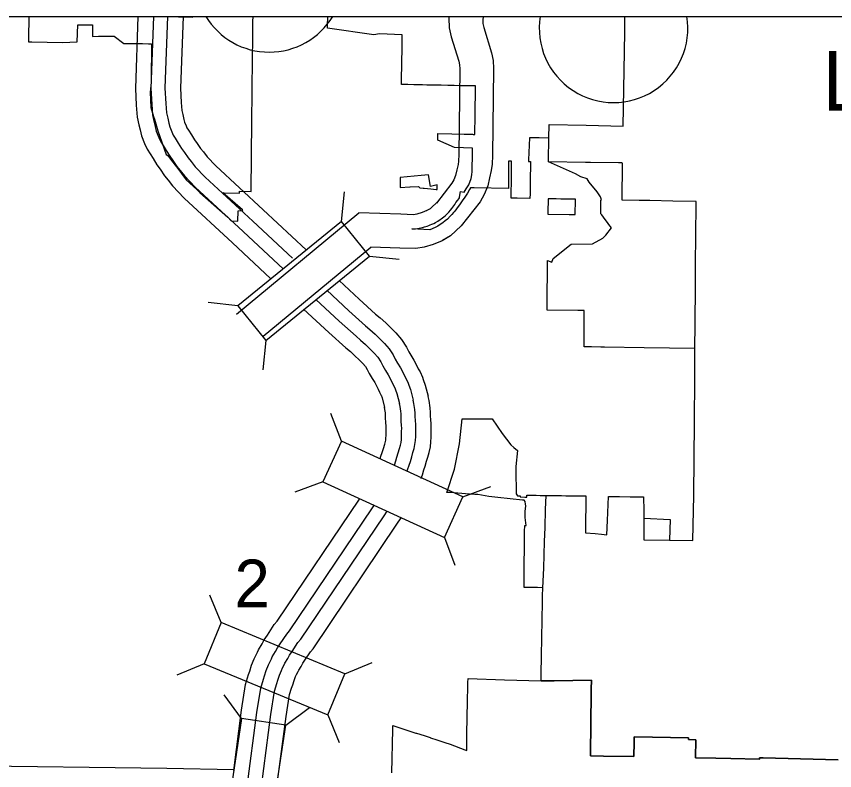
# Model space of a CAD drawing. Extents: x 670147 to 673275, y 705573 to 707613.
# Drawn here: x 670452.9 to 670561.9, y 707421.2 to 707521.7 of the extents above; entities that cross this region are included whole.
import ezdxf

# ---------------------------------------------------------------- set-up
doc = ezdxf.new("R2010")
doc.units = 0
for name, color, linetype in [('10', 7, 'Continuous'), ('19', 7, 'Continuous'), ('20', 7, 'Continuous'), ('27', 7, 'Continuous'), ('6', 7, 'Continuous'), ('R_NoPlot', 7, 'Continuous')]:
    doc.layers.add(name, color=color, linetype=linetype)

msp = doc.modelspace()

# ---------------------------------------------------------------- linework, layer by layer
at = {"layer": '10'}
for points in [[(670510.55, 707521.73), (670510.52, 707521.49), (670510.54, 707520.2), (670510.82, 707519.02), (670511.86, 707515.75), (670511.95, 707515.29), (670511.97, 707514.74), (670511.84, 707503.3), (670511.81, 707502.45), (670511.74, 707502.01), (670511.57, 707501.26), (670511.39, 707500.51), (670511.17, 707499.96), (670510.92, 707499.51), (670508.86, 707496.85)], [(670515.09, 707521.73), (670515.03, 707521.21), (670515.03, 707520.76), (670515.16, 707520.23), (670516.22, 707516.89), (670516.44, 707515.83), (670516.47, 707514.79), (670516.33, 707503.2), (670516.3, 707502.05), (670516.17, 707501.17), (670515.95, 707500.23), (670515.7, 707499.14), (670515.23, 707498), (670514.68, 707497.03), (670512.17, 707493.82)], [(670509.1, 707497.12), (670508.01, 707496.1), (670507.58, 707495.84), (670506.98, 707495.59), (670506.24, 707495.38), (670505.8, 707495.3), (670504.12, 707495.36), (670498.55, 707495.53)], [(670509.1, 707497.12), (670508.01, 707496.1), (670507.58, 707495.84), (670507.53, 707495.82)], [(670482.25, 707482.05), (670498.55, 707495.53)], [(670512.17, 707493.82), (670510.75, 707492.5), (670509.63, 707491.82), (670508.44, 707491.32), (670507.25, 707490.99), (670506.13, 707490.79), (670503.97, 707490.86), (670500.11, 707490.98)], [(670512.17, 707493.82), (670510.75, 707492.5), (670509.68, 707491.84)], [(670485.78, 707479.13), (670500.11, 707490.98)], [(670481.89, 707421.33), (670472.96, 707421.52), (670445.36, 707421.86)]]:
    msp.add_lwpolyline(points, dxfattribs=at)
at = {"layer": '19'}
for points in [[(670469.11, 707521.73), (670468.77, 707512.11), (670468.89, 707509.88), (670469.01, 707508.3), (670469.23, 707507.28), (670469.4, 707506.6), (670469.58, 707505.82), (670470, 707504.78), (670470.34, 707504.03), (670470.72, 707503.42), (670471.12, 707502.77), (670471.64, 707501.95), (670472.05, 707501.36), (670472.66, 707500.47), (670473.14, 707499.92), (670473.72, 707499.13), (670475.28, 707497.5), (670481.71, 707491.54), (670486.78, 707486.82)], [(670471.17, 707521.73), (670470.83, 707512.13), (670470.95, 707510.01), (670471.05, 707508.6), (670471.24, 707507.75), (670471.4, 707507.07), (670471.55, 707506.45), (670471.89, 707505.6), (670472.16, 707505.01), (670472.48, 707504.51), (670472.87, 707503.86), (670473.36, 707503.09), (670473.75, 707502.53), (670474.3, 707501.73), (670474.75, 707501.21), (670475.3, 707500.46), (670476.73, 707498.98), (670483.11, 707493.05), (670488.48, 707488.05)], [(670471.17, 707521.73), (670470.83, 707512.13), (670470.95, 707510.01), (670471.05, 707508.6), (670471.24, 707507.75), (670471.4, 707507.07), (670471.55, 707506.45), (670471.89, 707505.6), (670472.16, 707505.01), (670472.48, 707504.51), (670472.87, 707503.86), (670473.36, 707503.09), (670473.75, 707502.53), (670474.3, 707501.73), (670474.75, 707501.21), (670475.3, 707500.46), (670476.73, 707498.98), (670483.11, 707493.05), (670488.48, 707488.05)], [(670473.05, 707521.73), (670472.71, 707512.15), (670472.82, 707510.13), (670472.91, 707508.87), (670473.07, 707508.17), (670473.23, 707507.5), (670473.34, 707507.01), (670473.62, 707506.34), (670473.81, 707505.91), (670474.08, 707505.49), (670474.46, 707504.85), (670474.92, 707504.13), (670475.29, 707503.6), (670475.78, 707502.88), (670476.21, 707502.38), (670476.74, 707501.68), (670478.04, 707500.31), (670484.39, 707494.43), (670489.69, 707489.49)], [(670473.05, 707521.73), (670472.71, 707512.15), (670472.82, 707510.13), (670472.91, 707508.87), (670473.07, 707508.17), (670473.23, 707507.5), (670473.34, 707507.01), (670473.62, 707506.34), (670473.81, 707505.91), (670474.08, 707505.49), (670474.46, 707504.85), (670474.92, 707504.13), (670475.29, 707503.6), (670475.78, 707502.88), (670476.21, 707502.38), (670476.74, 707501.68), (670478.04, 707500.31), (670484.39, 707494.43), (670489.69, 707489.49)], [(670475.11, 707521.73), (670474.77, 707512.18), (670474.88, 707510.26), (670474.96, 707509.17), (670475.08, 707508.63), (670475.24, 707507.97), (670475.31, 707507.64), (670475.51, 707507.16), (670475.63, 707506.89), (670475.83, 707506.57), (670476.22, 707505.93), (670476.64, 707505.28), (670476.99, 707504.77), (670477.42, 707504.14), (670477.82, 707503.67), (670478.31, 707503.01), (670479.49, 707501.79), (670485.79, 707495.94), (670491.51, 707490.62)], [(670495.9, 707486.53), (670498.58, 707484.03), (670500.77, 707482.06), (670501.36, 707481.56), (670502.11, 707480.88), (670502.75, 707480.25), (670503.45, 707479.57), (670504.23, 707478.67), (670504.87, 707477.66), (670505.18, 707477.04), (670505.47, 707476.57), (670505.86, 707475.91), (670506.18, 707475.34), (670506.44, 707474.78), (670506.68, 707474.34), (670506.99, 707473.65), (670507.12, 707473.32), (670507.38, 707472.58), (670507.75, 707471.1)], [(670495.9, 707486.53), (670498.58, 707484.03), (670500.77, 707482.06), (670501.36, 707481.56), (670502.11, 707480.88), (670502.75, 707480.25), (670503.45, 707479.57), (670504.23, 707478.67), (670504.87, 707477.66), (670505.18, 707477.04), (670505.47, 707476.57), (670505.86, 707475.91), (670506.18, 707475.34), (670506.44, 707474.78), (670506.68, 707474.34), (670506.99, 707473.65), (670507.12, 707473.32), (670507.38, 707472.58), (670507.75, 707471.1)], [(670494.27, 707485.23), (670497.19, 707482.51), (670499.41, 707480.51), (670500, 707480.01), (670500.69, 707479.38), (670501.31, 707478.78), (670501.95, 707478.15), (670502.57, 707477.43), (670503.08, 707476.64), (670503.37, 707476.05), (670503.7, 707475.51), (670504.07, 707474.88), (670504.34, 707474.4), (670504.6, 707473.84), (670504.83, 707473.42), (670505.09, 707472.84), (670505.19, 707472.6), (670505.4, 707471.99), (670505.75, 707470.6)], [(670494.27, 707485.23), (670497.19, 707482.51), (670499.41, 707480.51), (670500, 707480.01), (670500.69, 707479.38), (670501.31, 707478.78), (670501.95, 707478.15), (670502.57, 707477.43), (670503.08, 707476.64), (670503.37, 707476.05), (670503.7, 707475.51), (670504.07, 707474.88), (670504.34, 707474.4), (670504.6, 707473.84), (670504.83, 707473.42), (670505.09, 707472.84), (670505.19, 707472.6), (670505.4, 707471.99), (670505.75, 707470.6)], [(670492.82, 707484.02), (670495.92, 707481.13), (670498.17, 707479.1), (670498.76, 707478.6), (670499.41, 707478.01), (670500, 707477.43), (670500.58, 707476.87), (670501.06, 707476.31), (670501.44, 707475.71), (670501.73, 707475.14), (670502.09, 707474.54), (670502.44, 707473.95), (670502.67, 707473.54), (670502.93, 707472.99), (670503.15, 707472.58), (670503.37, 707472.11), (670503.43, 707471.95), (670503.6, 707471.46), (670503.93, 707470.14)], [(670492.82, 707484.02), (670495.92, 707481.13), (670498.17, 707479.1), (670498.76, 707478.6), (670499.41, 707478.01), (670500, 707477.43), (670500.58, 707476.87), (670501.06, 707476.31), (670501.44, 707475.71), (670501.73, 707475.14), (670502.09, 707474.54), (670502.44, 707473.95), (670502.67, 707473.54), (670502.93, 707472.99), (670503.15, 707472.58), (670503.37, 707472.11), (670503.43, 707471.95), (670503.6, 707471.46), (670503.93, 707470.14)], [(670491.18, 707482.73), (670494.53, 707479.61), (670496.81, 707477.55), (670497.4, 707477.05), (670497.99, 707476.51), (670498.56, 707475.96), (670499.08, 707475.46), (670499.4, 707475.08), (670499.65, 707474.69), (670499.92, 707474.14), (670500.32, 707473.48), (670500.65, 707472.92), (670500.83, 707472.6), (670501.09, 707472.05), (670501.3, 707471.67), (670501.47, 707471.3), (670501.5, 707471.24), (670501.62, 707470.88), (670501.93, 707469.63)], [(670504.95, 707461.07), (670505.03, 707461.29), (670505.22, 707461.92), (670505.39, 707462.41), (670505.58, 707463.04), (670505.74, 707463.59), (670505.9, 707464.13), (670506.01, 707464.67), (670506.07, 707465.2), (670506.1, 707465.74), (670506.1, 707466.41), (670506.12, 707466.8), (670506.1, 707467.34), (670506.06, 707467.89), (670506.03, 707468.39), (670506.02, 707468.85), (670505.99, 707469.32), (670505.86, 707470.13), (670505.75, 707470.59)], [(670506.82, 707460.16), (670506.83, 707460.19), (670506.99, 707460.65), (670507.18, 707461.28), (670507.36, 707461.78), (670507.55, 707462.45), (670507.72, 707463), (670507.91, 707463.62), (670508.06, 707464.36), (670508.12, 707465.03), (670508.16, 707465.67), (670508.16, 707466.37), (670508.18, 707466.79), (670508.16, 707467.45), (670508.11, 707468.03), (670508.09, 707468.46), (670508.08, 707468.93), (670508.04, 707469.55), (670507.89, 707470.54), (670507.75, 707471.09)], [(670501.37, 707462.8), (670501.48, 707463.14), (670501.64, 707463.6), (670501.8, 707464.16), (670501.97, 707464.73), (670502.08, 707465.09), (670502.11, 707465.25), (670502.14, 707465.51), (670502.16, 707465.87), (670502.16, 707466.5), (670502.18, 707466.82), (670502.17, 707467.12), (670502.13, 707467.62), (670502.09, 707468.25), (670502.08, 707468.7), (670502.07, 707468.89), (670502, 707469.35), (670501.93, 707469.65)], [(670503.27, 707461.94), (670503.44, 707462.5), (670503.6, 707462.98), (670503.78, 707463.57), (670503.95, 707464.13), (670504.08, 707464.59), (670504.16, 707464.95), (670504.2, 707465.35), (670504.22, 707465.8), (670504.23, 707466.45), (670504.24, 707466.81), (670504.23, 707467.24), (670504.18, 707467.76), (670504.15, 707468.32), (670504.15, 707468.78), (670504.12, 707469.12), (670504.02, 707469.76), (670503.93, 707470.14)], [(670481.86, 707421.22), (670482.92, 707429.26), (670483.44, 707432.69), (670483.85, 707434.02), (670484, 707434.47), (670484.24, 707435.26), (670484.6, 707436.12), (670484.84, 707436.67), (670485.02, 707437), (670485.16, 707437.33), (670485.65, 707438.13), (670485.94, 707438.65), (670486.35, 707439.26), (670487.27, 707440.67), (670487.66, 707441.12), (670498.62, 707457.38), (670498.64, 707457.41)], [(670483.66, 707419.12), (670484.96, 707428.97), (670485.46, 707432.23), (670485.82, 707433.39), (670485.97, 707433.84), (670486.19, 707434.56), (670486.49, 707435.31), (670486.7, 707435.76), (670486.88, 707436.11), (670487, 707436.39), (670487.43, 707437.09), (670487.7, 707437.57), (670488.06, 707438.12), (670488.92, 707439.42), (670489.3, 707439.86), (670500.33, 707456.23), (670500.61, 707456.64)], [(670485.55, 707419.12), (670486.82, 707428.71), (670487.29, 707431.82), (670487.6, 707432.82), (670487.75, 707433.27), (670487.95, 707433.93), (670488.22, 707434.57), (670488.38, 707434.93), (670488.58, 707435.3), (670488.68, 707435.53), (670489.05, 707436.15), (670489.3, 707436.6), (670489.63, 707437.08), (670490.42, 707438.29), (670490.79, 707438.72), (670501.89, 707455.19), (670502.29, 707455.79)], [(670487.59, 707419.12), (670488.86, 707428.42), (670489.31, 707431.36), (670489.57, 707432.19), (670489.72, 707432.64), (670489.9, 707433.23), (670490.11, 707433.75), (670490.23, 707434.02), (670490.44, 707434.41), (670490.52, 707434.59), (670490.84, 707435.11), (670491.06, 707435.52), (670491.34, 707435.93), (670492.07, 707437.05), (670492.44, 707437.47), (670503.6, 707454.04), (670504.17, 707454.89)]]:
    msp.add_lwpolyline(points, dxfattribs=at)
at = {"layer": '20'}
for p, q in [((670496.23, 707494.39), (670496.64, 707498.33)), ((670499.97, 707489.78), (670503.91, 707489.37)), ((670482.39, 707483.17), (670478.45, 707483.58)), ((670486.13, 707478.55), (670485.72, 707474.61)), ((670496.2, 707465.1), (670494.81, 707468.81)), ((670496.2, 707465.1), (670494.81, 707468.81)), ((670493.73, 707459.7), (670490.02, 707458.31)), ((670493.73, 707459.7), (670490.02, 707458.31)), ((670512.4, 707457.7), (670516.12, 707459.08)), ((670512.4, 707457.7), (670516.12, 707459.08)), ((670509.94, 707452.29), (670511.32, 707448.58)), ((670480.2, 707440.95), (670478.68, 707444.6)), ((670496.66, 707434.13), (670500.32, 707435.64)), ((670477.93, 707435.46), (670474.27, 707433.94)), ((670482.92, 707428.15), (670480.57, 707431.34)), ((670488.8, 707427.27), (670491.98, 707429.62)), ((670494.39, 707428.64), (670495.91, 707424.98))]:
    msp.add_line(p, q, dxfattribs=at)
for points in [[(670486.13, 707478.55), (670499.97, 707489.78), (670496.23, 707494.39), (670482.39, 707483.17)], [(670493.73, 707459.7), (670509.94, 707452.29), (670512.4, 707457.7), (670496.2, 707465.1)], [(670496.66, 707434.13), (670480.2, 707440.95), (670477.93, 707435.46), (670494.39, 707428.64)], [(670482.92, 707428.15), (670480.28, 707410.53), (670486.15, 707409.65), (670488.8, 707427.27)]]:
    msp.add_lwpolyline(points, close=True, dxfattribs=at)
at = {"layer": '27'}
for centre, start, end in [((670486.6, 707526.86), 211.2192, 328.7808), ((670532.46, 707520.14), 170.78, 9.22)]:
    msp.add_arc(centre, 9.9, start, end, dxfattribs=at)
at = {"layer": '6'}
for points in [[(670454.57, 707521.73), (670454.54, 707518.73), (670454.53, 707518.33), (670454.99, 707518.33), (670459.05, 707518.26), (670461, 707518.32), (670461.08, 707520.61), (670462.71, 707520.6), (670463.04, 707520.62), (670463.05, 707519.63), (670463.06, 707519.03), (670463.85, 707519.07), (670464.52, 707519.08)], [(670464.52, 707519.08), (670465.93, 707519.11), (670467.23, 707518.13), (670469.7, 707518.1), (670470.5, 707518.09), (670470.9, 707518.08), (670470.89, 707513.1), (670470.87, 707512.94), (670470.72, 707511.62), (670470.82, 707509.59), (670471.19, 707508.39), (670471.29, 707508.01), (670471.75, 707506.49), (670472.88, 707503.32), (670473.07, 707503.18), (670473.58, 707502.53), (670474.25, 707501.67), (670474.27, 707501.64), (670475.53, 707499.96), (670476.93, 707498.66), (670477.36, 707498.27), (670481.06, 707494.96), (670481.54, 707494.47), (670482.41, 707494.46), (670482.46, 707495.83), (670483.06, 707495.86), (670483.02, 707495.94), (670480.42, 707498.22), (670480.57, 707498.22), (670482.62, 707498.18), (670482.62, 707498.43), (670484.17, 707498.4), (670484.27, 707507.86), (670484.28, 707508.02), (670484.28, 707508.24), (670484.29, 707509.41), (670484.3, 707509.95), (670484.31, 707510.48), (670484.31, 707511.02), (670484.32, 707511.55), (670484.33, 707512.09), (670484.33, 707512.62), (670484.34, 707513.16), (670484.34, 707513.7), (670484.35, 707514.24), (670484.36, 707514.77), (670484.36, 707515.3), (670484.37, 707515.84), (670484.38, 707516.56), (670484.38, 707516.93), (670484.39, 707517.89), (670484.4, 707518.9), (670484.41, 707519.69), (670484.42, 707520.38), (670484.43, 707521.06), (670484.44, 707521.73)], [(670476.35, 707521.73), (670476.35, 707521.59), (670474.49, 707521.62), (670474.49, 707521.73)], [(670512.01, 707496.76), (670511.53, 707496.09), (670511.31, 707495.79), (670511.15, 707495.59), (670510.93, 707495.33), (670510.71, 707495.09), (670510.32, 707494.72), (670510.05, 707494.48), (670509.72, 707494.23), (670509.37, 707493.99), (670509.04, 707493.79), (670508.71, 707493.61), (670508, 707493.28), (670505.61, 707493.4), (670506.09, 707493.43), (670506.57, 707493.5), (670506.95, 707493.58), (670507.02, 707493.61), (670507.29, 707493.68), (670507.61, 707493.77), (670507.84, 707493.85), (670508.04, 707493.93), (670508.26, 707494.03), (670508.51, 707494.14), (670508.73, 707494.26), (670509.07, 707494.45), (670509.35, 707494.64), (670509.51, 707494.75), (670509.66, 707494.86), (670509.84, 707495), (670510.01, 707495.15), (670510.16, 707495.28), (670510.34, 707495.46), (670510.5, 707495.63), (670510.76, 707495.92), (670510.92, 707496.13), (670511.31, 707496.65), (670511.47, 707496.92), (670511.71, 707497.24), (670511.86, 707497.42), (670511.94, 707497.53), (670511.95, 707497.63), (670512.06, 707498.38), (670512.56, 707498.32), (670512.82, 707498.73), (670513.19, 707499.3), (670513.47, 707500.11), (670513.57, 707500.63), (670513.63, 707501.06), (670513.63, 707501.37), (670513.64, 707502.13), (670513.65, 707502.54), (670513.66, 707504.16), (670511.28, 707504.24), (670509.04, 707505.21), (670509.06, 707506.1), (670510.91, 707506.06), (670512.54, 707506.03), (670513.66, 707506.01), (670513.78, 707506), (670513.99, 707506), (670514, 707507.05), (670514.01, 707507.5), (670514.03, 707508.44), (670514.08, 707512.45), (670513.84, 707512.46), (670512.09, 707512.49), (670511.23, 707512.51), (670510.4, 707512.52), (670509.5, 707512.54), (670509.21, 707512.55), (670508.64, 707512.56), (670507.82, 707512.57), (670507.57, 707512.58), (670506.99, 707512.59), (670506.63, 707512.6), (670505.96, 707512.61), (670505.84, 707512.61), (670505.05, 707512.63), (670504.21, 707512.64), (670504.22, 707513.2), (670504.22, 707513.24), (670504.22, 707513.29), (670504.28, 707517.61), (670504.3, 707518.22), (670504.31, 707519.29), (670501.3, 707519.4), (670500.51, 707519.25), (670494.36, 707520.17), (670494.36, 707520.44), (670494.38, 707521.73)], [(670543.15, 707457.89), (670543.23, 707467.68), (670543.28, 707473.49), (670543.3, 707476.44), (670543.3, 707477.47), (670543.33, 707480.72), (670543.37, 707485.8), (670543.38, 707487.26), (670543.38, 707487.52), (670543.39, 707489.09), (670543.41, 707492.13), (670543.42, 707492.16), (670543.45, 707497.05), (670540.35, 707497.11), (670537.29, 707497.17), (670535.89, 707497.19), (670533.59, 707497.23), (670533.67, 707502.18), (670533.54, 707502.19), (670533.11, 707502.19), (670529.4, 707502.26), (670528.74, 707502.27), (670523.81, 707502.36), (670523.81, 707502.55), (670523.85, 707505.5), (670523.88, 707507.31), (670528.81, 707507.21), (670533.75, 707507.11), (670533.9, 707516.99), (670533.94, 707519.72), (670533.98, 707521.73)], [(670524.95, 707457.87), (670525.51, 707457.86), (670526.08, 707457.85), (670527.03, 707457.84), (670528.77, 707457.82), (670528.76, 707456.7), (670528.75, 707455.79), (670528.74, 707455.22), (670528.74, 707454.66), (670528.73, 707453.7), (670528.72, 707453.17), (670528.72, 707452.92), (670529.99, 707452.82), (670530.83, 707452.75), (670531.56, 707452.63), (670531.65, 707454.55), (670531.78, 707457.77), (670531.78, 707457.77), (670533.24, 707457.75), (670534.66, 707457.72), (670536.22, 707457.69), (670536.43, 707457.69), (670536.47, 707455.86), (670536.49, 707454.88), (670540.02, 707454.69), (670539.93, 707451.91), (670543.02, 707451.89), (670543.15, 707457.89), (670543.23, 707467.68), (670543.28, 707473.49), (670543.3, 707476.44), (670543.3, 707477.47), (670536.55, 707477.58), (670531.24, 707477.67), (670530.75, 707477.67), (670529.51, 707477.69), (670528.53, 707477.7), (670528.54, 707482.54), (670528.28, 707482.54), (670527.8, 707482.55), (670527.7, 707482.55), (670523.61, 707482.59), (670523.61, 707485.36), (670523.64, 707486.91), (670523.64, 707487.59), (670523.65, 707488.46), (670523.65, 707488.8), (670523.66, 707489.21), (670524.22, 707488.98), (670524.43, 707489.48), (670526.83, 707491.36), (670529.67, 707491.43), (670531.05, 707492.19), (670531.43, 707492.58), (670532.18, 707493.53), (670531.85, 707493.99), (670531.73, 707494.14), (670531.13, 707494.95), (670530.88, 707495.27), (670530.76, 707495.42), (670530.78, 707496.37), (670530.78, 707497.23), (670530.85, 707497.28), (670530.73, 707497.69), (670530.28, 707498.36), (670529.22, 707499.63), (670528.93, 707500.08), (670528.08, 707500.34), (670527.38, 707500.74), (670523.81, 707502.36), (670523.81, 707502.55), (670523.85, 707505.5), (670522.54, 707505.53), (670521.26, 707505.55), (670521.13, 707502.6), (670521.12, 707502.41), (670521.39, 707502.41), (670521.39, 707502.14), (670521.38, 707501.31), (670521.37, 707500.67), (670521.36, 707500.04), (670521.35, 707499.4), (670521.34, 707498.76), (670521.33, 707498.12), (670521.32, 707497.46), (670519.64, 707497.49), (670519.3, 707497.5), (670518.81, 707497.52), (670518.85, 707500.45), (670518.87, 707502.45), (670518.48, 707502.45), (670518.47, 707500.28), (670518.47, 707498.81), (670513.89, 707498.88), (670513.42, 707498.89), (670513.28, 707498.64), (670513, 707498.19), (670512.66, 707497.63), (670512.31, 707497.16), (670512.01, 707496.76)], [(670504.92, 707426.63), (670506.13, 707426.23), (670506.19, 707426.22), (670507.23, 707425.88), (670508.02, 707425.62), (670508.08, 707425.6), (670508.94, 707425.32), (670509.99, 707424.97), (670510.71, 707424.74), (670512.66, 707423.97), (670512.9, 707423.88), (670512.93, 707426.69), (670512.95, 707427.72), (670512.97, 707428.81), (670513.02, 707429.95), (670513.01, 707430.92), (670513.06, 707431.97), (670513.05, 707432.96), (670513.08, 707433.5), (670517.91, 707433.31), (670522.81, 707433.19), (670522.88, 707437.42), (670522.89, 707438.02), (670522.9, 707438.33), (670522.9, 707438.62), (670522.91, 707439.22), (670522.92, 707439.82), (670522.93, 707440.42), (670522.94, 707441.02), (670522.96, 707441.62), (670522.97, 707442.22), (670522.98, 707442.82), (670522.99, 707443.42), (670523, 707444.15), (670523, 707444.53), (670523.05, 707445.57), (670522.33, 707445.6), (670521.73, 707445.61), (670521.57, 707445.61), (670521.13, 707445.62), (670520.53, 707445.63), (670520.53, 707445.91), (670520.54, 707446.51), (670520.54, 707447.11), (670520.55, 707447.71), (670520.56, 707448.31), (670520.56, 707448.91), (670520.57, 707449.51), (670520.58, 707450.11), (670520.58, 707450.71), (670520.59, 707451.31), (670520.6, 707451.91), (670520.61, 707452.5), (670520.61, 707453.1), (670520.63, 707453.9), (670520.82, 707453.89), (670520.68, 707454.97), (670520.67, 707455.74), (670520.76, 707456.5), (670520.73, 707456.74), (670520.67, 707457.09), (670520.55, 707457.25), (670520.33, 707457.28), (670517.03, 707457.62), (670515.86, 707457.77), (670514.36, 707458.02), (670514, 707458.03), (670513.27, 707458.08), (670510.68, 707458.26), (670510.23, 707458.3), (670511.25, 707461.41), (670511.94, 707464.75), (670512.3, 707468.1), (670513.41, 707468.08), (670515.34, 707468.08), (670516.29, 707468.08), (670517.64, 707466.16), (670518.79, 707464.64), (670519.18, 707464.29), (670519.67, 707463.86), (670519.45, 707461.74), (670519.45, 707461.33), (670519.45, 707461.29), (670519.47, 707458.1), (670519.58, 707457.97), (670519.68, 707457.85), (670520.02, 707457.85), (670520.02, 707457.69), (670520.63, 707457.68), (670520.91, 707457.68), (670520.91, 707457.86), (670520.91, 707457.92), (670521.58, 707457.91), (670522.14, 707457.91), (670522.7, 707457.9), (670523.26, 707457.89), (670523.47, 707457.89), (670523.83, 707457.88), (670524.39, 707457.88), (670524.95, 707457.87)], [(670562.37, 707422.67), (670557.36, 707422.79), (670552.4, 707422.91), (670552.36, 707422.91), (670551.91, 707422.92), (670551.91, 707422.74), (670551.86, 707422.74), (670548.1, 707422.82), (670546.09, 707422.87), (670543.38, 707422.94), (670543.42, 707425.33), (670542.44, 707425.37), (670542.44, 707425.61), (670537.63, 707425.68), (670535.22, 707425.72), (670535.22, 707425.52), (670535.21, 707424.99), (670535.18, 707423.08), (670531.11, 707423.16), (670529.38, 707423.18), (670529.39, 707423.97), (670529.4, 707424.98), (670529.41, 707426), (670529.42, 707427.01), (670529.43, 707428.01), (670529.45, 707429.02), (670529.46, 707430.04), (670529.48, 707431.05), (670529.49, 707432.08), (670529.5, 707433.27), (670524.55, 707433.18), (670522.81, 707433.19), (670522.88, 707437.42), (670522.89, 707438.02), (670522.9, 707438.33), (670522.9, 707438.62), (670522.91, 707439.22), (670522.92, 707439.82), (670522.93, 707440.42), (670522.94, 707441.02), (670522.96, 707441.62), (670522.97, 707442.22), (670522.98, 707442.82), (670522.99, 707443.42), (670523, 707444.15), (670523, 707444.53), (670523.05, 707445.57), (670523.17, 707448.22), (670523.28, 707451.74), (670523.34, 707453.6), (670523.41, 707456.01), (670523.47, 707457.89), (670523.83, 707457.88), (670524.39, 707457.88), (670524.95, 707457.87), (670525.51, 707457.86), (670526.08, 707457.85), (670527.03, 707457.84), (670528.77, 707457.82), (670528.76, 707456.7), (670528.75, 707455.79), (670528.74, 707455.22), (670528.74, 707454.66), (670528.73, 707453.7), (670528.72, 707453.17), (670528.72, 707452.92), (670529.99, 707452.82), (670530.83, 707452.75), (670531.56, 707452.63), (670531.65, 707454.55), (670531.78, 707457.77), (670531.78, 707457.77), (670533.24, 707457.75), (670534.66, 707457.72), (670536.22, 707457.69), (670536.43, 707457.69), (670536.47, 707455.86), (670536.49, 707454.88), (670536.5, 707454.55), (670536.48, 707453.58), (670536.47, 707451.96), (670539.93, 707451.91), (670543.02, 707451.89), (670543.15, 707457.89)], [(670512.97, 707428.81), (670513.02, 707429.95), (670513.01, 707430.92), (670513.06, 707431.97), (670513.05, 707432.96), (670513.08, 707433.5), (670517.91, 707433.31), (670522.81, 707433.19), (670524.55, 707433.18), (670529.5, 707433.27), (670529.49, 707432.08), (670529.48, 707431.05), (670529.46, 707430.04), (670529.45, 707429.02), (670529.43, 707428.01), (670529.42, 707427.01), (670529.41, 707426), (670529.4, 707424.98), (670529.39, 707423.97), (670529.38, 707423.18), (670531.11, 707423.16), (670535.18, 707423.08), (670535.21, 707424.99), (670535.22, 707425.52), (670535.22, 707425.72), (670537.63, 707425.68), (670542.44, 707425.61), (670542.44, 707425.37), (670543.42, 707425.33), (670543.38, 707422.94), (670546.09, 707422.87), (670548.1, 707422.82), (670551.86, 707422.74), (670551.91, 707422.74), (670551.91, 707422.92), (670552.36, 707422.91), (670552.4, 707422.91), (670557.36, 707422.79), (670562.37, 707422.67)], [(670502.92, 707420.92), (670503.05, 707426.7), (670503.05, 707427.24), (670503.2, 707427.19), (670504.92, 707426.63), (670506.13, 707426.23), (670506.19, 707426.22), (670507.23, 707425.88), (670508.02, 707425.62), (670508.08, 707425.6), (670508.94, 707425.32), (670509.99, 707424.97), (670510.71, 707424.74), (670512.66, 707423.97), (670512.9, 707423.88), (670512.93, 707426.69), (670512.95, 707427.72), (670512.97, 707428.81)], [(670502.92, 707420.92), (670503.05, 707426.7), (670503.05, 707427.24), (670503.2, 707427.19), (670504.92, 707426.63)]]:
    msp.add_lwpolyline(points, dxfattribs=at)
for points in [[(670508.95, 707498.67), (670508.98, 707499.03), (670508.96, 707499.29), (670508.06, 707499.04), (670507.82, 707500.63), (670506.82, 707500.52), (670504.05, 707500.24), (670504.04, 707498.91), (670505.33, 707499.02), (670505.37, 707499.02), (670506.47, 707499.06), (670506.66, 707498.89), (670507.09, 707498.85), (670507.23, 707498.84), (670508.12, 707498.74), (670508.83, 707498.67)], [(670527.36, 707495.31), (670527.37, 707497.29), (670527.37, 707497.35), (670526.56, 707497.36), (670526.18, 707497.37), (670525.44, 707497.38), (670524.8, 707497.4), (670524.16, 707497.41), (670523.74, 707497.42), (670523.72, 707495.6), (670523.72, 707495.37), (670526.55, 707495.32)]]:
    msp.add_lwpolyline(points, close=True, dxfattribs=at)
at = {"layer": 'R_NoPlot'}
msp.add_lwpolyline([(670257.19, 707521.73), (670842.89, 707521.73), (670842.89, 706992.57), (670257.19, 706992.57)], close=True, dxfattribs=at)

# ---------------------------------------------------------------- texts
at = {"layer": '20'}
msp.add_text('2', height=6.34, dxfattribs=at).set_placement((670481.96, 707443))
at = {"layer": '6'}
msp.add_text('LITTLE', height=7.92, dxfattribs=at).set_placement((670560.29, 707509.18))

doc.saveas('drawing.dxf')
